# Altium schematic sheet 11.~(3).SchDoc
size 398 x 287 mm
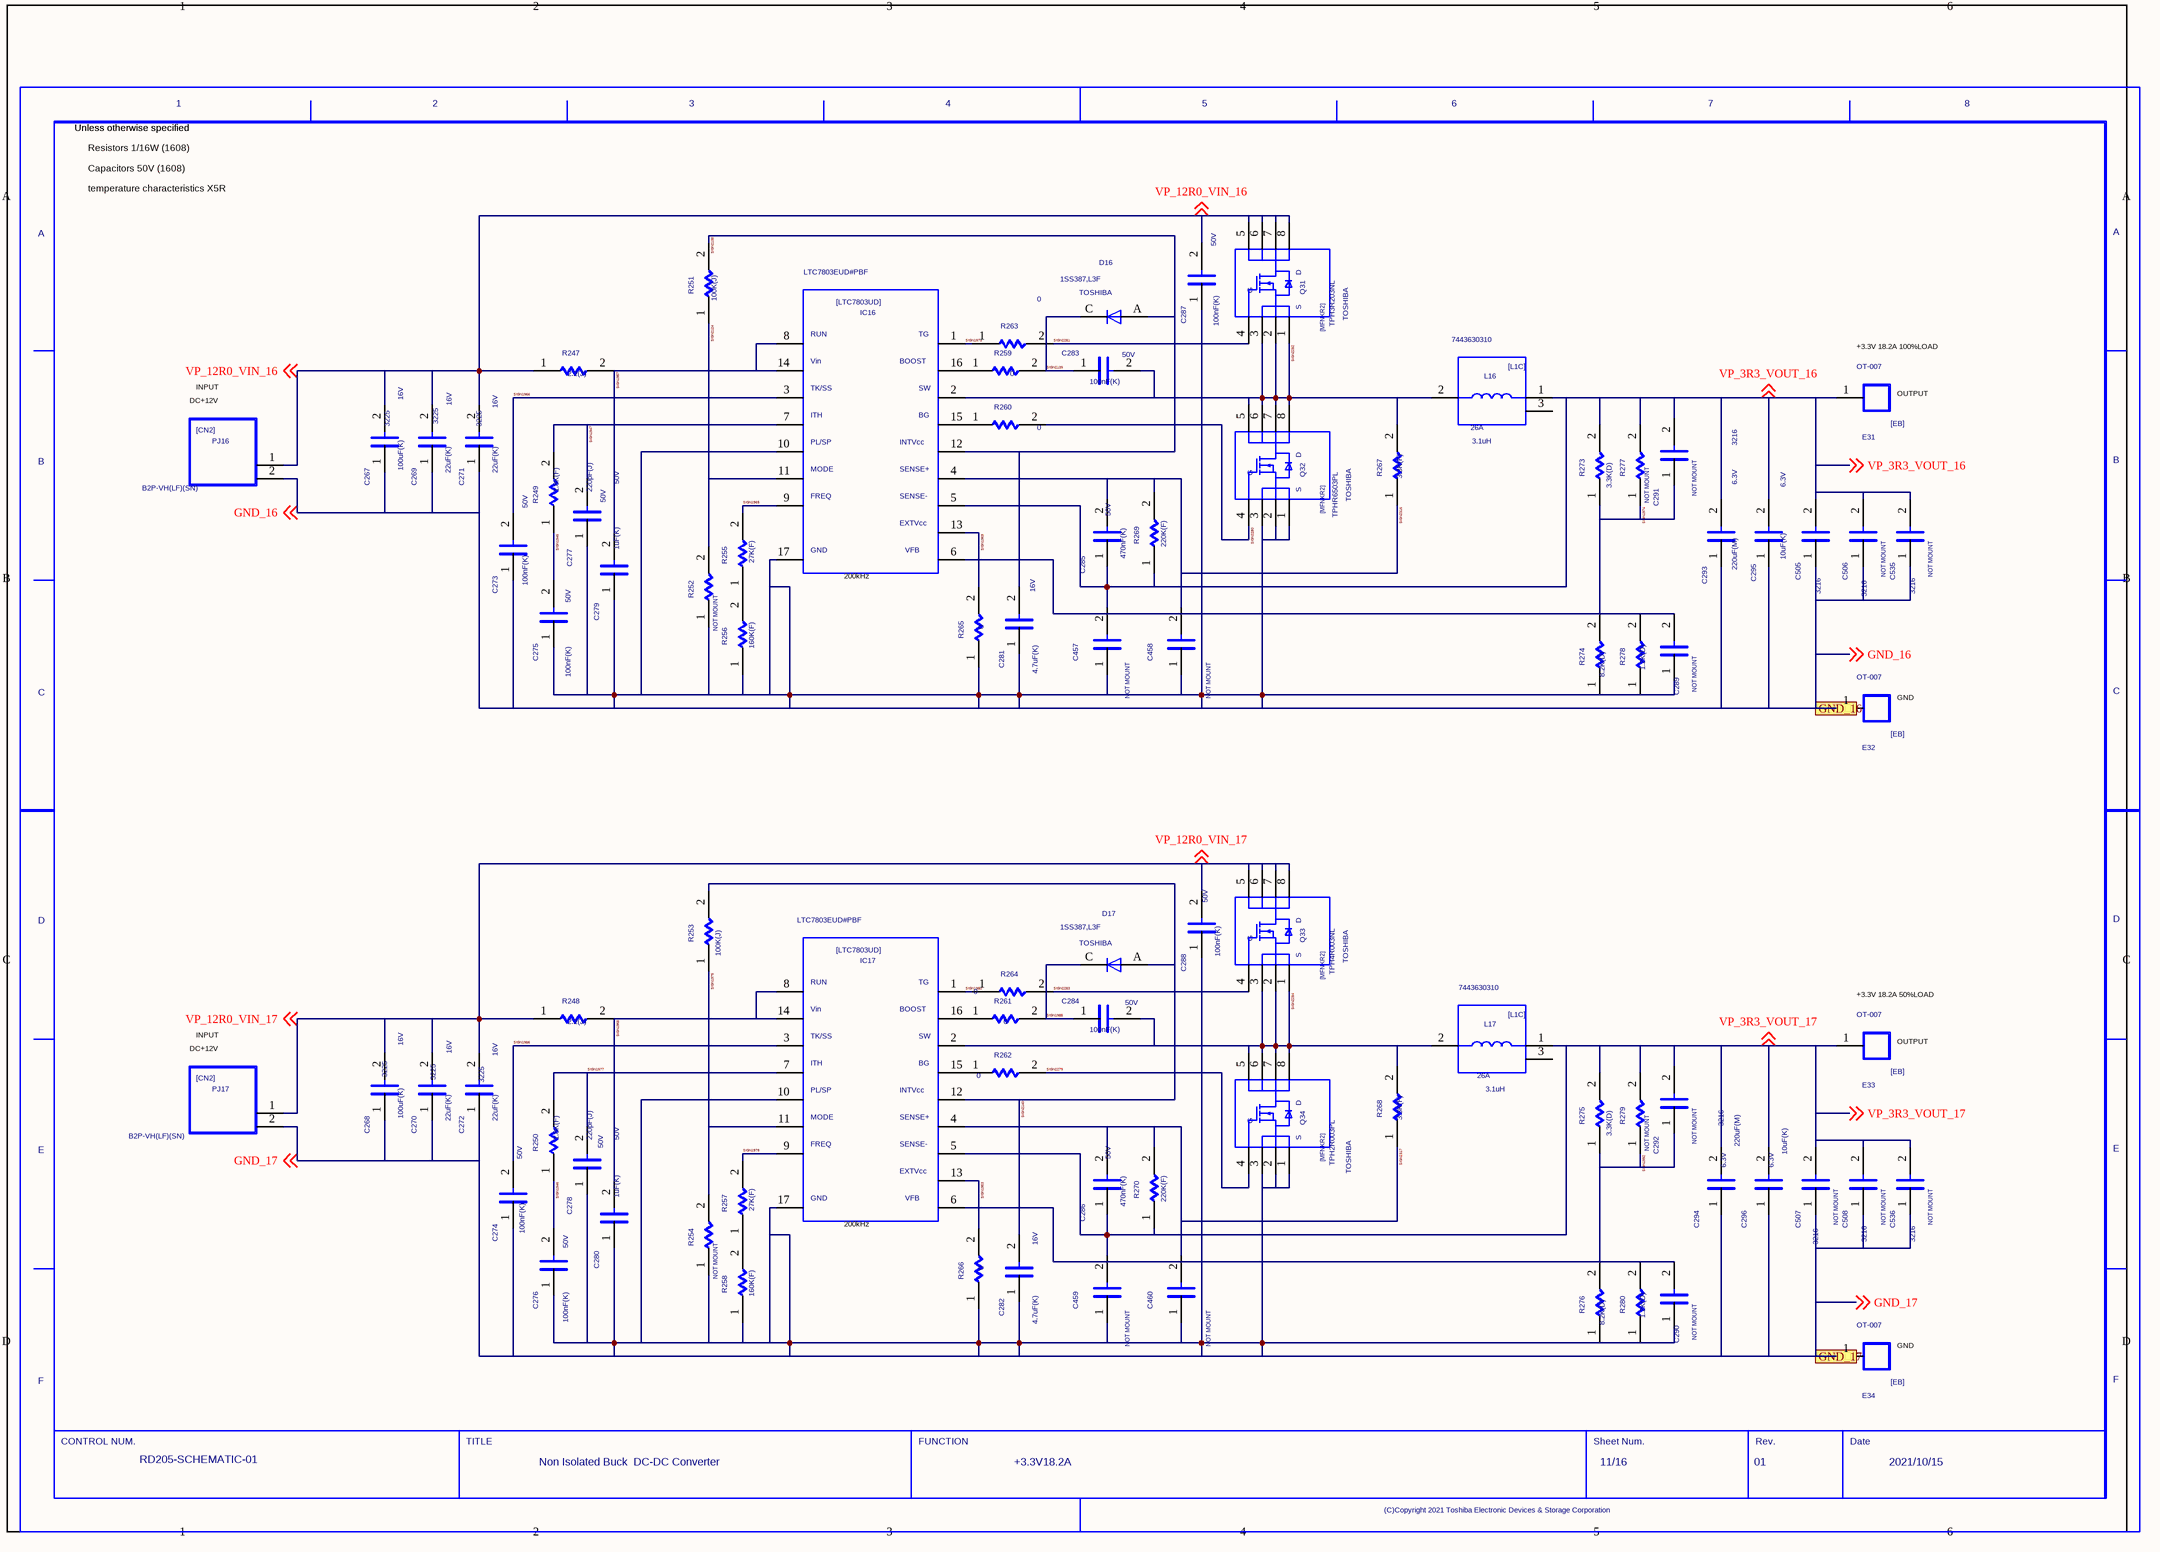
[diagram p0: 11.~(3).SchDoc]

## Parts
C267  SIZECODESMD: 3225  VAL2: 16V  VAL1: 100uF(K)  (hidden comment: C)
C268  SIZECODESMD: 3225  VAL2: 16V  VAL1: 100uF(K)  (hidden comment: C)
C269  SIZECODESMD: 3225  VAL2: 16V  VAL1: 22uF(K)  (hidden comment: C)
C270  SIZECODESMD: 3225  VAL2: 16V  VAL1: 22uF(K)  (hidden comment: C)
C271  SIZECODESMD: 3225  VAL2: 16V  VAL1: 22uF(K)  (hidden comment: C)
C272  SIZECODESMD: 3225  VAL2: 16V  VAL1: 22uF(K)  (hidden comment: C)
C273  VAL2: 50V  VAL1: 100nF(K)  (hidden comment: C)
C274  VAL2: 50V  VAL1: 100nF(K)  (hidden comment: C)
C275  VAL2: 50V  VAL1: 100nF(K)  (hidden comment: C)
C276  VAL2: 50V  VAL1: 100nF(K)  (hidden comment: C)
C277  VAL2: 50V  VAL1: 220pF(J)  (hidden comment: C)
C278  VAL2: 50V  VAL1: 220pF(J)  (hidden comment: C)
C279  VAL2: 50V  VAL1: 1uF(K)  (hidden comment: C)
C280  VAL2: 50V  VAL1: 1uF(K)  (hidden comment: C)
C281  VAL2: 16V  VAL1: 4.7uF(K)  (hidden comment: C)
C282  VAL2: 16V  VAL1: 4.7uF(K)  (hidden comment: C)
C283  VAL2: 50V  VAL1: 100nF(K)  (hidden comment: C)
C284  VAL2: 50V  VAL1: 100nF(K)  (hidden comment: C)
C285  VAL2: 50V  VAL1: 470nF(K)  (hidden comment: C)
C286  VAL2: 50V  VAL1: 470nF(K)  (hidden comment: C)
C287  VAL2: 50V  VAL1: 100nF(K)  (hidden comment: C)
C288  VAL2: 50V  VAL1: 100nF(K)  (hidden comment: C)
C289  NOTMOUNT: NOT MOUNT  (hidden comment: C)
C290  NOTMOUNT: NOT MOUNT  (hidden comment: C)
C291  NOTMOUNT: NOT MOUNT  (hidden comment: C)
C292  NOTMOUNT: NOT MOUNT  (hidden comment: C)
C293  SIZECODESMD: 3216  VAL2: 6.3V  VAL1: 220uF(M)  (hidden comment: C)
C294  SIZECODESMD: 3216  VAL2: 6.3V  VAL1: 220uF(M)  (hidden comment: C)
C295  VAL2: 6.3V  VAL1: 10uF(K)  (hidden comment: C)
C296  VAL2: 6.3V  VAL1: 10uF(K)  (hidden comment: C)
C457  NOTMOUNT: NOT MOUNT  (hidden comment: C)
C458  NOTMOUNT: NOT MOUNT  (hidden comment: C)
C459  NOTMOUNT: NOT MOUNT  (hidden comment: C)
C460  NOTMOUNT: NOT MOUNT  (hidden comment: C)
C505  SIZECODESMD: 3216  (hidden comment: C)
C506  NOTMOUNT: NOT MOUNT  SIZECODESMD: 3216  (hidden comment: C)
C507  NOTMOUNT: NOT MOUNT  SIZECODESMD: 3216  (hidden comment: C)
C508  NOTMOUNT: NOT MOUNT  SIZECODESMD: 3216  (hidden comment: C)
C535  NOTMOUNT: NOT MOUNT  SIZECODESMD: 3216  (hidden comment: C)
C536  NOTMOUNT: NOT MOUNT  SIZECODESMD: 3216  (hidden comment: C)
D16  COMPCOMMENT: TOSHIBA  VAL3: 1SS387,L3F  (hidden comment: D)
D17  USERCOMPTEXT3: TOSHIBA  VAL3: 1SS387,L3F  (hidden comment: D)
E31  VAL3: OT-007  (hidden comment: EB)
E32  VAL3: OT-007  (hidden comment: EB)
E33  VAL3: OT-007  (hidden comment: EB)
E34  VAL3: OT-007  (hidden comment: EB)
IC16  VAL3: LTC7803EUD#PBF  (hidden comment: LTC7803UD)
IC17  VAL3: LTC7803EUD#PBF  (hidden comment: LTC7803UD)
L16  VAL3: 7443630310  VAL2: 26A  VAL1: 3.1uH  (hidden comment: L1C)
L17  VAL3: 7443630310  VAL2: 26A  VAL1: 3.1uH  (hidden comment: L1C)
PJ16  VAL3: B2P-VH(LF)(SN)  (hidden comment: CN2)
PJ17  VAL3: B2P-VH(LF)(SN)  (hidden comment: CN2)
Q31  USERCOMPTEXT3: TOSHIBA  VAL3: TPH3R203NL  (hidden comment: MFNKR2)
Q32  USERCOMPTEXT3: TOSHIBA  VAL3: TPHR6503PL  (hidden comment: MFNKR2)
Q33  USERCOMPTEXT3: TOSHIBA  VAL3: TPH4R003NL  (hidden comment: MFNKR2)
Q34  USERCOMPTEXT3: TOSHIBA  VAL3: TPH2R003PL  (hidden comment: MFNKR2)
R247  VAL1: 2.2(J)  (hidden comment: R)
R248  VAL1: 2.2(J)  (hidden comment: R)
R249  VAL1: 1.8K(F)  (hidden comment: R)
R250  VAL1: 1.8K(F)  (hidden comment: R)
R251  VAL1: 100K(J)  (hidden comment: R)
R252  NOTMOUNT: NOT MOUNT  (hidden comment: R)
R253  VAL1: 100K(J)  (hidden comment: R)
R254  NOTMOUNT: NOT MOUNT  (hidden comment: R)
R255  VAL1: 27K(F)  (hidden comment: R)
R256  VAL1: 160K(F)  (hidden comment: R)
R257  VAL1: 27K(F)  (hidden comment: R)
R258  VAL1: 160K(F)  (hidden comment: R)
R259  VAL1: 0  (hidden comment: R)
R260  VAL1: 0  (hidden comment: R)
R261  VAL1: 0  (hidden comment: R)
R262  VAL1: 0  (hidden comment: R)
R263  VAL1: 0  (hidden comment: R)
R264  VAL1: 0  (hidden comment: R)
R265  VAL1: 0  (hidden comment: R)
R266  VAL1: 0  (hidden comment: R)
R267  VAL1: 3.3K(F)  (hidden comment: R)
R268  VAL1: 3.3K(F)  (hidden comment: R)
R269  VAL1: 220K(F)  (hidden comment: R)
R270  VAL1: 220K(F)  (hidden comment: R)
R273  VAL1: 3.3K(D)  (hidden comment: R)
R274  VAL1: 8.2K(D)  (hidden comment: R)
R275  VAL1: 3.3K(D)  (hidden comment: R)
R276  VAL1: 8.2K(D)  (hidden comment: R)
R277  NOTMOUNT: NOT MOUNT  (hidden comment: R)
R278  VAL1: 1.2K(D)  (hidden comment: R)
R279  NOTMOUNT: NOT MOUNT  (hidden comment: R)
R280  VAL1: 1.2K(D)  (hidden comment: R)
U?  DATE: 2021/10/15  SHEETNUMBER: 11/16  TITLE: Non Isolated Buck / DC-DC Converter  REVISION: 01  DRAWINGNUMBER: RD205-SCHEMATIC-01  FUNCTION: +3.3V18.2A  (hidden comment: WAKU_DEF100)

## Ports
GND_16, GND_17

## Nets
GND_16: C267.1 C269.1 C271.1 C273.1 C275.1 C277.1 C279.1 C281.1 C287.1 C289.1 C293.1 C295.1 C457.1 C458.1 C505.1 C506.1 C535.1 E32.1 IC16.10 IC16.17 PJ16.2 Q32.1 Q32.2 Q32.3 R252.1 R256.1 R265.1 R274.1 R278.1 ; off-sheet GND_16, port GND_16
GND_17: C268.1 C270.1 C272.1 C274.1 C276.1 C278.1 C280.1 C282.1 C288.1 C290.1 C294.1 C296.1 C459.1 C460.1 C507.1 C508.1 C536.1 E34.1 IC17.10 IC17.17 PJ17.2 Q34.1 Q34.2 Q34.3 R254.1 R258.1 R266.1 R276.1 R280.1 ; off-sheet GND_17, port GND_17
SIGN1945: C275.2 R249.1
SIGN1946: C276.2 R250.1
SIGN1947: C277.2 IC16.7 R249.2
SIGN1953: IC17.13 R266.2
SIGN1957: C279.2 IC16.8 IC16.14 R247.2
SIGN1965: IC16.9 R255.2
SIGN1966: C273.2 IC16.3
SIGN1968: C280.2 IC17.8 IC17.14 R248.2
SIGN1969: IC16.13 R265.2
SIGN1973: IC16.1 R263.1
SIGN1974: C289.2 C291.1 IC16.6 R273.1 R274.2 R277.1 R278.2
SIGN1975: IC17.11 R253.1 R254.2
SIGN1977: C278.2 IC17.7 R250.2
SIGN1978: IC17.9 R257.2
SIGN1980: IC17.1 R264.1
SIGN1985: C284.1 D17.C R261.2
SIGN1986: C274.2 IC17.3
SIGN1992: C290.2 C292.1 IC17.6 R275.1 R276.2 R279.1 R280.2
SIGN2124: IC16.11 R251.1 R252.2
SIGN2138: C281.2 D16.A IC16.12 R251.2
SIGN2139: C283.1 D16.C R259.2
SIGN2140: C282.2 D17.A IC17.12 R253.2
SIGN2279: Q34.4 R262.2
SIGN2280: Q32.4 R260.2
SIGN2281: Q31.4 R263.2
SIGN2282: C283.2 IC16.2 L16.2 Q31.1 Q31.2 Q31.3 Q32.5 Q32.6 Q32.7 Q32.8 R267.2
SIGN2283: Q33.4 R264.2
SIGN2284: C284.2 IC17.2 L17.2 Q33.1 Q33.2 Q33.3 Q34.5 Q34.6 Q34.7 Q34.8 R268.2
SIGN2316: C285.2 C458.2 IC16.4 R267.1 R269.2
SIGN2317: C286.2 C460.2 IC17.4 R268.1 R270.2
VP_3R3_VOUT_16: C285.1 C291.2 C293.2 C295.2 C457.2 C505.2 C506.2 C535.2 E31.1 IC16.5 L16.1 R269.1 R273.2 R277.2 ; off-sheet VP_3R3_VOUT_16
VP_3R3_VOUT_17: C286.1 C292.2 C294.2 C296.2 C459.2 C507.2 C508.2 C536.2 E33.1 IC17.5 L17.1 R270.1 R275.2 R279.2 ; off-sheet VP_3R3_VOUT_17
VP_12R0_VIN_16: C267.2 C269.2 C271.2 C287.2 PJ16.1 Q31.5 Q31.6 Q31.7 Q31.8 R247.1 ; off-sheet VP_12R0_VIN_16
VP_12R0_VIN_17: C268.2 C270.2 C272.2 C288.2 PJ17.1 Q33.5 Q33.6 Q33.7 Q33.8 R248.1 ; off-sheet VP_12R0_VIN_17
NetIC16_15: IC16.15 R260.1
NetIC16_16: IC16.16 R259.1
NetIC17_15: IC17.15 R262.1
NetIC17_16: IC17.16 R261.1
NetR255_1: R255.1 R256.2
NetR257_1: R257.1 R258.2

Not connected (* = marked no-connect by the designer): L16 3; L17 3

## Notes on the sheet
- Unless otherwise specified
- Resistors 1/16W (1608)
- Capacitors 50V (1608)
- temperature characteristics X5R
- DC+12V
- INPUT
- (near E31) +3.3V 18.2A 100%LOAD
- (near E31) OUTPUT
- (near IC16) 200kHz
- (near E32) GND
- (near E33) +3.3V 18.2A 50%LOAD
- (near E33) OUTPUT
- (near IC17) 200kHz
- (near E34) GND

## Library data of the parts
C267 C268 = C: SQ_PART_MODEL: CON_100n; FNPARTSNAMEG: CHIP CERAMIC CAPACITOR (3225); USEINPARTSLIST: YES; OriginalSymbolOrigin: (2540,7620); MFSOLDERINGPROP: .; TEMPCHARACTERI2: B; MFFORMINGDIVP: KC; OUMECLASSIFICATION: セラミックコンデンサ; MFMOUNTSYMBOLP: 90; CDMASTERCADCELG: DC903A; PCODE: P03276001115; FNCLASSCODEG: P03-03; MAXGCOUNT: 1; RATEDVOLTAGE: 250; COMPONENTNAME: G36030160049; OUMEMAKER: KYC 京セラ; MFPACKAGEMETHOP: S; NOMINALCAPACITA: 100n; OUMEMAKERKATAMEI: CF32W5R104K250AT; CAPACITANCETOLE: K
C269-C272 = C: SQ_PART_MODEL: CON_22u; FNPARTSNAMEG: CHIP CERAMIC CAPACITOR (3225); USEINPARTSLIST: YES; OriginalSymbolOrigin: (2540,7620); MFSOLDERINGPROP: .; TEMPCHARACTERI2: B; MFFORMINGDIVP: KC; OUMECLASSIFICATION: セラミックコンデンサ; MFMOUNTSYMBOLP: 80; CDMASTERCADCELG: DC903A; PCODE: P03043035626; FNCLASSCODEG: P03-03; MAXGCOUNT: 1; RATEDVOLTAGE: 6.3; COMPONENTNAME: G36030119054; OUMEMAKER: TYD 太陽誘電; MFPACKAGEMETHOP: S; NOMINALCAPACITA: 22u; OUMEMAKERKATAMEI: JMK325BJ226KM-T; CAPACITANCETOLE: K
C273-C276 C283 C284 C287 C288 = C: SQ_PART_MODEL: CON_100n; FNPARTSNAMEG: CHIP CERAMIC CAPACITOR (1608); USEINPARTSLIST: YES; OriginalSymbolOrigin: (2540,7620); MFSOLDERINGPROP: .; TEMPCHARACTERI2: B; MFFORMINGDIVP: KC; OUMECLASSIFICATION: セラミックコンデンサ; SIZECODESMD: 1608; MFMOUNTSYMBOLP: 80; CDMASTERCADCELG: C8100E; PCODE: P03B000000E4; FNCLASSCODEG: P03-03; MAXGCOUNT: 1; RATEDVOLTAGE: 16; COMPONENTNAME: GDM030000598; OUMEMAKER: MRT 村田製作所; MFPACKAGEMETHOP: S; NOMINALCAPACITA: 100n; OUMEMAKERKATAMEI: GRM188B11C104KA01C; CAPACITANCETOLE: K
C277 C278 = C: SQ_PART_MODEL: CON_220p; FNPARTSNAMEG: CHIP CERAMIC CAPACITOR (1608); USEINPARTSLIST: YES; OriginalSymbolOrigin: (2540,7620); CDMASTERCADCELG: C8100E; MFSOLDERINGPROP: .; TEMPCHARACTERI2: CH; MFFORMINGDIVP: KC; OUMECLASSIFICATION: セラミックコンデンサ; SIZECODESMD: 1608; MFMOUNTSYMBOLP: 80; PCODE: P03039269127; FNCLASSCODEG: P03-03; MAXGCOUNT: 1; RATEDVOLTAGE: 50; COMPONENTNAME: GDM030000578; OUMEMAKER: KYC 京セラ; MFPACKAGEMETHOP: S; NOMINALCAPACITA: 220p; OUMEMAKERKATAMEI: CM105CH221J50AT; CAPACITANCETOLE: J
C279 C280 = C: SQ_PART_MODEL: CON_1u; FNPARTSNAMEG: CHIP CERAMIC CAPACITOR (1608); USEINPARTSLIST: YES; OriginalSymbolOrigin: (2540,7620); MFSOLDERINGPROP: .; TEMPCHARACTERI2: B; MFFORMINGDIVP: KC; OUMECLASSIFICATION: セラミックコンデンサ; SIZECODESMD: 1608; MFMOUNTSYMBOLP: 80; CDMASTERCADCELG: C8100E; PCODE: P03039ACE122; FNCLASSCODEG: P03-03; MAXGCOUNT: 1; RATEDVOLTAGE: 6.3; COMPONENTNAME: G36030104159; OUMEMAKER: KYC 京セラ; MFPACKAGEMETHOP: S; NOMINALCAPACITA: 1u; OUMEMAKERKATAMEI: CM105B105K06ATN; CAPACITANCETOLE: K
C281 C282 = C: SQ_PART_MODEL: CON_4.7u; FNPARTSNAMEG: CHIP CERAMIC CAPACITOR (1608); USEINPARTSLIST: YES; OriginalSymbolOrigin: (2540,7620); MFSOLDERINGPROP: .; TEMPCHARACTERI2: B; MFFORMINGDIVP: KC; OUMECLASSIFICATION: セラミックコンデンサ; SIZECODESMD: 1608; MFMOUNTSYMBOLP: 80; CDMASTERCADCELG: C8100E; PCODE: P03B000000MS; FNCLASSCODEG: P03-03; MAXGCOUNT: 1; RATEDVOLTAGE: 4; COMPONENTNAME: GDM030000053; OUMEMAKER: KYC 京セラ; MFPACKAGEMETHOP: S; NOMINALCAPACITA: 4.7u; OUMEMAKERKATAMEI: CM105B475M04AT; CAPACITANCETOLE: M
C285 C286 = C: SQ_PART_MODEL: CON_470n; FNPARTSNAMEG: CHIP CERAMIC CAPACITOR (1608); USEINPARTSLIST: YES; OriginalSymbolOrigin: (2540,7620); MFSOLDERINGPROP: .; TEMPCHARACTERI2: B; MFFORMINGDIVP: KC; OUMECLASSIFICATION: セラミックコンデンサ; SIZECODESMD: 1608; MFMOUNTSYMBOLP: 80; CDMASTERCADCELG: C8100E; PCODE: P03039ABG127; FNCLASSCODEG: P03-03; MAXGCOUNT: 1; RATEDVOLTAGE: 10; COMPONENTNAME: GDM030001129; OUMEMAKER: KYC 京セラ; MFPACKAGEMETHOP: S; NOMINALCAPACITA: 470n; OUMEMAKERKATAMEI: CM105B474K10AT; CAPACITANCETOLE: K
C289-C292 = C: SQ_PART_MODEL: CON_100p; FNPARTSNAMEG: CHIP CERAMIC CAPACITOR (1608); USEINPARTSLIST: YES; OriginalSymbolOrigin: (2540,7620); TOLERANCE: J; ASIMVALUE: 100P; MFSOLDERINGPROP: .; TEMPCHARACTERI2: CH; MFFORMINGDIVP: KC; OUMECLASSIFICATION: セラミックコンデンサ; SIZECODESMD: 1608; MFMOUNTSYMBOLP: 80; CDMASTERCADCELG: C8100E; PCODE: P03039177125; FNCLASSCODEG: P03-03; MAXGCOUNT: 1; RATEDVOLTAGE: 50; COMPONENTNAME: G36030011365; OUMEMAKER: KYC 京セラ; MFPACKAGEMETHOP: S; OUMEMAKERKATAMEI: CM105CH101J50AT; VAL2: 50V; VAL1: 100pF(J)
C293 C294 = C: SQ_PART_MODEL: CON_22u; FNPARTSNAMEG: CHIP CERAMIC CAPACITOR (3216); USEINPARTSLIST: YES; OriginalSymbolOrigin: (2540,7620); MFSOLDERINGPROP: .; TEMPCHARACTERI2: B; MFFORMINGDIVP: KC; OUMECLASSIFICATION: セラミックコンデンサ; MFMOUNTSYMBOLP: 80; CDMASTERCADCELG: DC901A; PCODE: P03B0000004V; FNCLASSCODEG: P03-03; MAXGCOUNT: 1; RATEDVOLTAGE: 6.3; COMPONENTNAME: GDM030000020; OUMEMAKER: KYC 京セラ; MFPACKAGEMETHOP: S; NOMINALCAPACITA: 22u; OUMEMAKERKATAMEI: CM316B226M06AT; CAPACITANCETOLE: M
C295 C296 = C: SQ_PART_MODEL: CON_1u; FNPARTSNAMEG: CHIP CERAMIC CAPACITOR (1608); PARTCOMMENT: 代表セル<KC0008> がフットプリントに登録されていません。; USEINPARTSLIST: YES; OriginalSymbolOrigin: (2540,7620); MFSOLDERINGPROP: .; TEMPCHARACTERI2: B; MFFORMINGDIVP: KC; OUMECLASSIFICATION: セラミックコンデンサ; SIZECODESMD: 1608; MFMOUNTSYMBOLP: 80; CDMASTERCADCELG: KC0008; PCODE: P03B000000ZQ; FNCLASSCODEG: P03-03; MAXGCOUNT: 1; RATEDVOLTAGE: 6.3; COMPONENTNAME: GDM030000202; OUMEMAKER: MRT 村田製作所; MFPACKAGEMETHOP: S; NOMINALCAPACITA: 1u; OUMEMAKERKATAMEI: GRM185B10J105KE21D; CAPACITANCETOLE: K
C457-C460 = C: SQ_PART_MODEL: CON_220n; FNPARTSNAMEG: CHIP CERAMIC CAPACITOR (1608); PARTCOMMENT: 代表セル<KC0008> がフットプリントに登録されていません。; USEINPARTSLIST: YES; OriginalSymbolOrigin: (2540,7620); MFSOLDERINGPROP: .; TEMPCHARACTERI2: B; MFFORMINGDIVP: KC; OUMECLASSIFICATION: セラミックコンデンサ; SIZECODESMD: 1608; MFMOUNTSYMBOLP: 80; CDMASTERCADCELG: KC0008; PCODE: P03B000001L3; FNCLASSCODEG: P03-03; MAXGCOUNT: 1; RATEDVOLTAGE: 16; COMPONENTNAME: GDM030001129; OUMEMAKER: MRT 村田製作所; MFPACKAGEMETHOP: S; NOMINALCAPACITA: 220n; OUMEMAKERKATAMEI: GRM188B11C224KA01D; VAL2: 16V; VAL1: 220nF(K); CAPACITANCETOLE: K
C505 = C: SQ_PART_MODEL: CON_22u; FNPARTSNAMEG: CHIP CERAMIC CAPACITOR (3216); USEINPARTSLIST: YES; OriginalSymbolOrigin: (2540,7620); NOTMOUNT: NOT MOUNT; MFSOLDERINGPROP: .; TEMPCHARACTERI2: B; MFFORMINGDIVP: KC; OUMECLASSIFICATION: セラミックコンデンサ; MFMOUNTSYMBOLP: 80; CDMASTERCADCELG: DC901A; PCODE: P03B0000004V; FNCLASSCODEG: P03-03; MAXGCOUNT: 1; RATEDVOLTAGE: 6.3; COMPONENTNAME: GDM030000020; OUMEMAKER: KYC 京セラ; MFPACKAGEMETHOP: S; NOMINALCAPACITA: 22u; OUMEMAKERKATAMEI: CM316B226M06AT; VAL2: 6.3V; VAL1: 22uF(M); CAPACITANCETOLE: M
C506-C508 C535 C536 = C: SQ_PART_MODEL: CON_22u; FNPARTSNAMEG: CHIP CERAMIC CAPACITOR (3216); USEINPARTSLIST: YES; OriginalSymbolOrigin: (2540,7620); MFSOLDERINGPROP: .; TEMPCHARACTERI2: B; MFFORMINGDIVP: KC; OUMECLASSIFICATION: セラミックコンデンサ; MFMOUNTSYMBOLP: 80; CDMASTERCADCELG: DC901A; PCODE: P03B0000004V; FNCLASSCODEG: P03-03; MAXGCOUNT: 1; RATEDVOLTAGE: 6.3; COMPONENTNAME: GDM030000020; OUMEMAKER: KYC 京セラ; MFPACKAGEMETHOP: S; NOMINALCAPACITA: 22u; OUMEMAKERKATAMEI: CM316B226M06AT; VAL2: 6.3V; VAL1: 22uF(M); CAPACITANCETOLE: M
D16 D17 = D: FNPARTSNAMEG: DIODE; USEINPARTSLIST: YES; PARTNAME: GDM420000143; SAVEAREA0: -565,-171,12979,8058; SAVECOUNT: 1; TIME: 14:49:55; UPDATEUSER: 19870035; UPDATETIME: 14:20:16; OriginalSymbolOrigin: (5080,5080); FORWARDVOLTAGEM: 0; MAXREVERSEVOLTA: 80; COMPONENTNAME: GDM420000143_package; MFSOLDERINGPROP: .; OUMEMAKER: TSB 東芝（ＹＰＳＳ）; QUADMODEL: dummymodel; MFPACKAGEMETHOP: S; MFFORMINGDIVP: MM; MOUNTINGFORMSMD: SMD; OUMECLASSIFICATION: 小信号ダイオード; OUMEMAKERKATAMEI: 1SS387(TPH3,F); CDMASTERCADCELG: D8101D; PCODE: P42B0000008E; FNCLASSCODEG: P42-01
E31-E34 = EB: FNPARTSNAMEG: TERMINAL; USEINPARTSLIST: YES; PARTNAME: 5P9L1232P001; OUMEPARTTYPE: TB; OriginalSymbolOrigin: (2540,12700); COMPONENTNAME: 5P9L1232P001_package; MAXGCOUNT: 1; MFSOLDERINGPROP: .; OUMEMAKER: オサダ; QUADMODEL: dummymodel; MFPACKAGEMETHOP: I; MFFORMINGDIVP: OD; OUMECLASSIFICATION: 端子台、端子板; CDMASTERCADCELG: DE0009; KIND: PBS; PCODE: P29045001117; TERMINALSTYLE: SC; FNCLASSCODEG: P29-01
IC16 IC17 = LTC7803UD: USEINPARTSLIST: YES; SAVECOUNT: 29; SAVEAREA0: -53177,0,89020,58420; TIME: 16:14:14; UPDATEUSER: q91866sr; UPDATETIME: 13:15:36; OriginalSymbolOrigin: (5080,55880); MAXGCOUNT: 1; COMPONENTNAME: LTC7803UD_LTC7803UD; OUMEMAKER: ANALOG DEVICES
L16 L17 = L1C: USEINPARTSLIST: YES; PARTNAME: 7443630140; SAVECOUNT: 6; SAVEAREA0: -5636,-341,27978,18652; OriginalSymbolOrigin: (5080,15240); COMPONENTNAME: L1C_L1C; MAXGCOUNT: 1; OUMEMAKER: WURTH
PJ16 PJ17 = CN2: FNPARTSNAMEG: 3.96PITCH NYLON CONNECTOR; USEINPARTSLIST: YES; PARTNAME: G36220114012; OUMEPARTTYPE: CN; OriginalSymbolOrigin: (2540,15240); MAXGCOUNT: 1; RATEDCURRENT: 7; COMPONENTNAME: G36220114012_package; MFSOLDERINGPROP: .; OUMEMAKER: JST 日本圧着端子製造; NUMBEROFCONTACT: 2; QUADMODEL: dummymodel; MFPACKAGEMETHOP: I; MFFORMINGDIVP: CU; CONTACTPITCH: 3.96m; OUMEMAKERKATAMEI: B2P-VH; CDMASTERCADCELG: DPJ514; PCODE: P22346001114; TERMINALSTYLE: PW; FNCLASSCODEG: P22-10
Q31-Q34 = MFNKR2: USEINPARTSLIST: YES; PARTNAME: TPH6R003NL; SAVEAREA0: -9199,-39,32138,22820; TIME: 18:57:44; UPDATEUSER: q91866sr; UPDATETIME: 12:36:02; SAVECOUNT: 10; OriginalSymbolOrigin: (5080,20320); MAXGCOUNT: 1; COMPONENTNAME: MFNKR2_MFNKR2
R247 R248 = R: SQ_PART_MODEL: RES_2.2; FNPARTSNAMEG: CHIP RESISTOR (1608); USEINPARTSLIST: YES; OriginalSymbolOrigin: (5080,5080); TOLERANCE: J; ASIMVALUE: 2.2; MAXGCOUNT: 1; COMPONENTNAME: G36010011507; MFSOLDERINGPROP: .; OUMEMAKER: NAE 松下電子部品; MFPACKAGEMETHOP: S; MFFORMINGDIVP: KC; MOUNTINGFORMSMD: SMD; OUMECLASSIFICATION: 表面実装用固定抵抗器; MFMOUNTSYMBOLP: 80; POWERRATING: 63m; OUMEMAKERKATAMEI: ERJ3GEYJ2R2V; NUMBEROFELEMENT: 0; VAL2: 62.5mW; CDMASTERCADCELG: DR802R; PCODE: P01042157622; FNCLASSCODEG: P01-08
R249 R250 = R: SQ_PART_MODEL: RES_1.8K; FNPARTSNAMEG: CHIP RESISTOR (1608); USEINPARTSLIST: YES; OriginalSymbolOrigin: (5080,5080); TOLERANCE: F; ASIMVALUE: 1.8K; MAXGCOUNT: 1; COMPONENTNAME: G36010104056; MFSOLDERINGPROP: .; OUMEMAKER: HDK 北陸電気工業; MFPACKAGEMETHOP: S; MFFORMINGDIVP: KC; MOUNTINGFORMSMD: SMD; OUMECLASSIFICATION: 表面実装用固定抵抗器; MFMOUNTSYMBOLP: 80; POWERRATING: 63m; OUMEMAKERKATAMEI: CR1/16 182FV; NUMBEROFELEMENT: 0; VAL2: 62.5mW; CDMASTERCADCELG: DR802R; PCODE: P01042030222; FNCLASSCODEG: P01-08
R251 R253 = R: SQ_PART_MODEL: RES_100K; FNPARTSNAMEG: CHIP RESISTOR (1608); USEINPARTSLIST: YES; OriginalSymbolOrigin: (5080,5080); TOLERANCE: J; ASIMVALUE: 100K; MFSOLDERINGPROP: .; MFPACKAGEMETHOP: S; MFFORMINGDIVP: KC; MOUNTINGFORMSMD: SMD; MFMOUNTSYMBOLP: 80; NUMBEROFELEMENT: 0; PCODE: P01042047220; MAXGCOUNT: 1; COMPONENTNAME: G36010011057; OUMEMAKER: HDK 北陸電気工業; OUMECLASSIFICATION: 表面実装用固定抵抗器; POWERRATING: 63m; OUMEMAKERKATAMEI: CR1/16 104JV; VAL2: 62.5mW; CDMASTERCADCELG: DR802R; FNCLASSCODEG: P01-08
R252 R254 = R: SQ_PART_MODEL: RES_10; FNPARTSNAMEG: CHIP RESISTOR (1608); USEINPARTSLIST: YES; OriginalSymbolOrigin: (5080,5080); TOLERANCE: F; ASIMVALUE: 10; MFSOLDERINGPROP: .; MFPACKAGEMETHOP: S; MFFORMINGDIVP: KC; MOUNTINGFORMSMD: SMD; MFMOUNTSYMBOLP: 80; NUMBEROFELEMENT: 0; PCODE: P01042036620; MAXGCOUNT: 1; COMPONENTNAME: G36010104063; OUMEMAKER: NAE 松下電子部品; OUMECLASSIFICATION: 表面実装用固定抵抗器; POWERRATING: 63m; OUMEMAKERKATAMEI: ERJ3GEYF100V; VAL2: 62.5mW; VAL1: 10(F); CDMASTERCADCELG: DR802R; FNCLASSCODEG: P01-08
R255 R257 = R: SQ_PART_MODEL: RES_27K; FNPARTSNAMEG: CHIP RESISTOR (1608); USEINPARTSLIST: YES; OriginalSymbolOrigin: (5080,5080); MAXGCOUNT: 1; TOLERANCE: F; COMPONENTNAME: G36010027195; MFSOLDERINGPROP: .; OUMEMAKER: NAE 松下電子部品; MFPACKAGEMETHOP: S; MFFORMINGDIVP: KC; MOUNTINGFORMSMD: SMD; OUMECLASSIFICATION: 表面実装用固定抵抗器; ASIMVALUE: 27K; MFMOUNTSYMBOLP: 80; POWERRATING: 63m; OUMEMAKERKATAMEI: ERJ3GEYF273V; NUMBEROFELEMENT: 0; VAL2: 62.5mW; CDMASTERCADCELG: DR802R; PCODE: P01042508622; FNCLASSCODEG: P01-08
R256 R258 = R: SQ_PART_MODEL: RES_160K; FNPARTSNAMEG: CHIP RESISTOR (1608); USEINPARTSLIST: YES; OriginalSymbolOrigin: (5080,5080); MAXGCOUNT: 1; COMPONENTNAME: G51011061108; MFSOLDERINGPROP: .; OUMEMAKER: HDK 北陸電気工業; MFPACKAGEMETHOP: S; MFFORMINGDIVP: KC; MOUNTINGFORMSMD: SMD; OUMECLASSIFICATION: 表面実装用固定抵抗器; RESISTANCETOLER: F; MFMOUNTSYMBOLP: 80; POWERRATING: 63m; OUMEMAKERKATAMEI: CR1/16 164FV; NOMINALRESISTAN: 160K; NUMBEROFELEMENT: 0; VAL2: 62.5mW; CDMASTERCADCELG: DR802R; PCODE: P01042125225; FNCLASSCODEG: P01-08
R259 R261 R265 R266 = R: SQ_PART_MODEL: RES_10; FNPARTSNAMEG: CHIP RESISTOR (1608); USEINPARTSLIST: YES; OriginalSymbolOrigin: (5080,5080); TOLERANCE: F; ASIMVALUE: 10; MFSOLDERINGPROP: .; MFPACKAGEMETHOP: S; MFFORMINGDIVP: KC; MOUNTINGFORMSMD: SMD; MFMOUNTSYMBOLP: 80; PCODE: P01042036620; MAXGCOUNT: 1; COMPONENTNAME: G36010104063; OUMEMAKER: NAE 松下電子部品; OUMECLASSIFICATION: 表面実装用固定抵抗器; POWERRATING: 63m; OUMEMAKERKATAMEI: ERJ3GEYF100V; VAL2: 62.5mW; CDMASTERCADCELG: DR802R; FNCLASSCODEG: P01-08
R260 R262-R264 = R: SQ_PART_MODEL: RES_10; FNPARTSNAMEG: CHIP RESISTOR (2012); USEINPARTSLIST: YES; OriginalSymbolOrigin: (5080,5080); MAXGCOUNT: 1; TOLERANCE: F; COMPONENTNAME: 5P9L1083P100; MFSOLDERINGPROP: .; OUMEMAKER: 北陸電気工業; MFPACKAGEMETHOP: S; MFFORMINGDIVP: KC; MOUNTINGFORMSMD: SMD; OUMECLASSIFICATION: 表面実装用固定抵抗器; ASIMVALUE: 10; MFMOUNTSYMBOLP: 90; POWERRATING: 100m; OUMEMAKERKATAMEI: CR1/10 100FV Pb(F); VAL2: 125mW; CDMASTERCADCELG: DR910A; PCODE: P01043091222; FNCLASSCODEG: P01-08
R267 R268 = R: SQ_PART_MODEL: RES_3.3K; FNPARTSNAMEG: CHIP RESISTOR (1608); USEINPARTSLIST: YES; OriginalSymbolOrigin: (5080,5080); TOLERANCE: F; ASIMVALUE: 3.3K; MAXGCOUNT: 1; COMPONENTNAME: G5101105R107; MFSOLDERINGPROP: .; OUMEMAKER: ROH ロー・; MFPACKAGEMETHOP: S; MFFORMINGDIVP: KC; MOUNTINGFORMSMD: SMD; OUMECLASSIFICATION: 表面実装用固定抵抗器; MFMOUNTSYMBOLP: 80; POWERRATING: 63m; OUMEMAKERKATAMEI: MCR03EZPFX3301; NUMBEROFELEMENT: 0; VAL2: 62.5mW; CDMASTERCADCELG: DR802R; PCODE: P01042250729; FNCLASSCODEG: P01-08
R269 R270 = R: SQ_PART_MODEL: RES_220K; FNPARTSNAMEG: CHIP RESISTOR (1608); USEINPARTSLIST: YES; OriginalSymbolOrigin: (5080,5080); MAXGCOUNT: 1; COMPONENTNAME: G51011062105; MFSOLDERINGPROP: .; OUMEMAKER: NAE 松下電子部品; MFPACKAGEMETHOP: S; MFFORMINGDIVP: KC; MOUNTINGFORMSMD: SMD; OUMECLASSIFICATION: 表面実装用固定抵抗器; RESISTANCETOLER: F; MFMOUNTSYMBOLP: 80; POWERRATING: 63m; OUMEMAKERKATAMEI: ERJ3GEYF224V; NOMINALRESISTAN: 220K; NUMBEROFELEMENT: 0; VAL2: 62.5mW; CDMASTERCADCELG: DR802R; PCODE: P01042202629; FNCLASSCODEG: P01-08
R273 R275 = R: SQ_PART_MODEL: RES_3.3K; FNPARTSNAMEG: CHIP RESISTOR (1608); USEINPARTSLIST: YES; OriginalSymbolOrigin: (5080,5080); MAXGCOUNT: 1; COMPONENTNAME: G36010014485; MFSOLDERINGPROP: .; OUMEMAKER: SSM 進工業; MFPACKAGEMETHOP: S; MFFORMINGDIVP: KC; MOUNTINGFORMSMD: SMD; OUMECLASSIFICATION: 表面実装用固定抵抗器; RESISTANCETOLER: D; MFMOUNTSYMBOLP: 80; POWERRATING: 63m; OUMEMAKERKATAMEI: RR0816P-332-D; NOMINALRESISTAN: 3.3K; NUMBEROFELEMENT: 0; VAL2: 62.5mW; CDMASTERCADCELG: DR802R; PCODE: P01042249822; FNCLASSCODEG: P01-08
R274 R276 = R: ICX_PART_MODEL: RES_8.2K; FNPARTSNAMEG: CHIP RESISTOR (1608); OriginalSymbolOrigin: (5080,5080); FNCLASSCODEG: P01-08; PCODE: P01117051114; CDMASTERCADCELG: DR802R; USEWITHSCHEMA: YES; VAL2: 62.5mW; NUMBEROFELEMENT: 0; NOMINALRESISTAN: 8.2K; OUMEMAKERKATAMEI: RK73G1JTD822D; POWERRATING: 63m; MFMOUNTSYMBOLP: 80; RESISTANCETOLER: D; FUNCTION: G36010129479; OUMECLASSIFICATION: 表面実装用固定抵抗器; MOUNTINGFORMSMD: SMD; MFFORMINGDIVP: KC; MFPACKAGEMETHOP: S; OUMEMAKER: KOA ＫＯＡ; MFSOLDERINGPROP: .; MAXGCOUNT: 1
R277 R279 = R: SQ_PART_MODEL: RES_3.3K; FNPARTSNAMEG: CHIP RESISTOR (1608); USEINPARTSLIST: YES; OriginalSymbolOrigin: (5080,5080); TOLERANCE: F; ASIMVALUE: 3.3K; MAXGCOUNT: 1; COMPONENTNAME: G36010027027; MFSOLDERINGPROP: .; OUMEMAKER: ROH ロー・; MFPACKAGEMETHOP: S; MFFORMINGDIVP: KC; MOUNTINGFORMSMD: SMD; OUMECLASSIFICATION: 表面実装用固定抵抗器; MFMOUNTSYMBOLP: 80; POWERRATING: 63m; OUMEMAKERKATAMEI: MCR03EZPFX3301; NUMBEROFELEMENT: 0; VAL2: 62.5mW; VAL1: 3.3K(F); CDMASTERCADCELG: DR802R; PCODE: P01042250729; FNCLASSCODEG: P01-08
R278 R280 = R: ICX_PART_MODEL: RES_1.2K; FNPARTSNAMEG: CHIP RESISTOR (1608); OriginalSymbolOrigin: (5080,5080); FNCLASSCODEG: P01-08; PCODE: P01117031116; CDMASTERCADCELG: DR802R; USEWITHSCHEMA: YES; VAL2: 62.5mW; NUMBEROFELEMENT: 0; NOMINALRESISTAN: 1.2K; OUMEMAKERKATAMEI: RK73G1JTD122D; POWERRATING: 63m; MFMOUNTSYMBOLP: 80; RESISTANCETOLER: D; FUNCTION: G36010129271; OUMECLASSIFICATION: 表面実装用固定抵抗器; MOUNTINGFORMSMD: SMD; MFFORMINGDIVP: KC; MFPACKAGEMETHOP: S; OUMEMAKER: KOA ＫＯＡ; MFSOLDERINGPROP: .; MAXGCOUNT: 1
U? = WAKU_DEF100: PLOTTIME: HH:MM; SAVEAREA0: 330961,54,387907,31546; TIME: 19:23:07; UPDATEUSER: t5459927; UPDATETIME: 15:33:41; SAVECOUNT: 6; OriginalSymbolOrigin: (10160,284480); DESIGNED: ***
